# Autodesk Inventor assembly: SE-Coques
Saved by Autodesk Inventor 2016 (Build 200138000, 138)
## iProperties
Created: 2013-08
Part Number: SE-Coques
Document SubType Name: Assembly
Designer: hilarion
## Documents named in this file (5)
- S:\TSTI2D\Documents en consultation\etude de cas 1  webcam\Webcam motorisee\SE-Coques.iam
- S:\TSTI2D\Documents en consultation\etude de cas 1  webcam\Webcam motorisee\Coque avant.ipt
- S:\TSTI2D\Documents en consultation\etude de cas 1  webcam\Webcam motorisee\Coque arriere.ipt
- S:\TSTI2D\Documents en consultation\etude de cas 1  webcam\Webcam motorisee\ensemble_mobile axe y.iam
- S:\TSTI2D\Documents en consultation\etude de cas 1  webcam\Webcam motorisee\Roue dentée Intermédiaire 12.ipt
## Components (4 placed, 4 different names)
1. Coque avant:1
2. Coque arriere:1
3. ensemble_mobile axe y:1 [sub-assembly]
4. Roue dentée Intermédiaire 12:1
